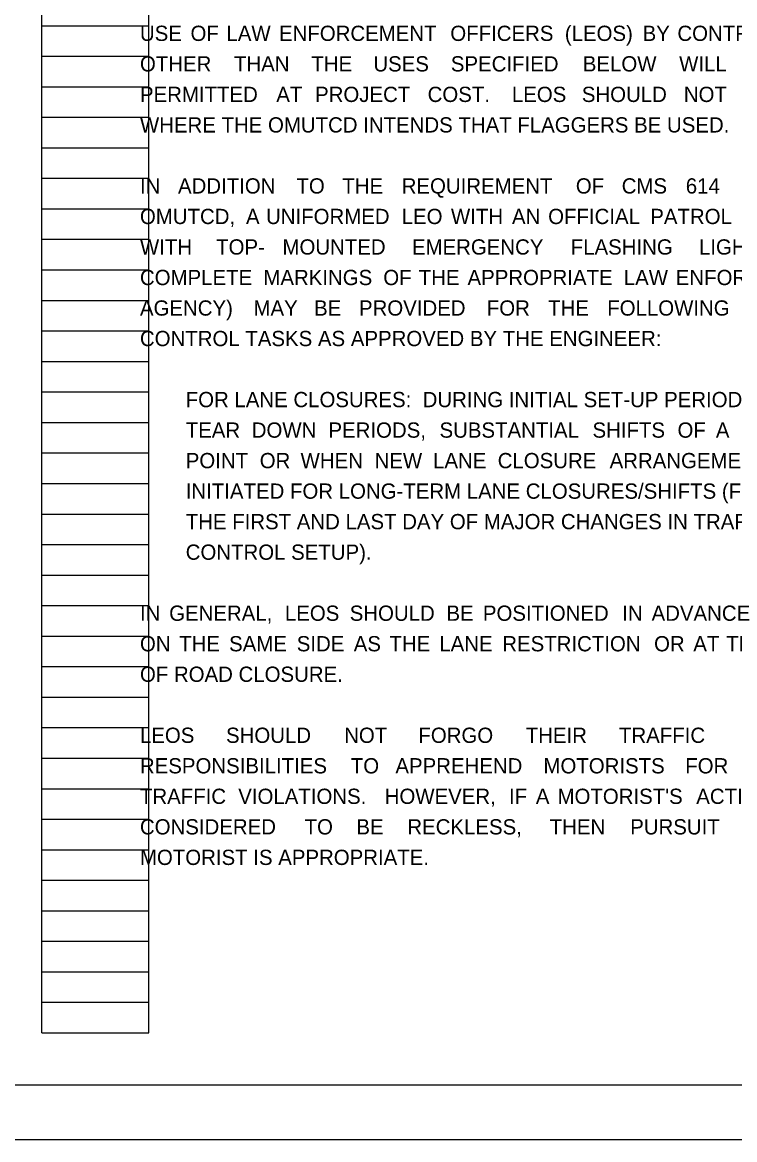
# Model space of a CAD drawing. Extents: x 0 to 34, y 0 to 22.
# Drawn here: x 23.5 to 30.04, y 0 to 10.25 of the extents above; entities that cross this region are included whole.
import ezdxf

# ---------------------------------------------------------------- set-up
doc = ezdxf.new("R2010")
doc.units = 0
for name, color, linetype in [('SH_Border', 7, 'Continuous'), ('SH_Cut_Line', 7, 'Continuous'), ('SH_Data', 7, 'Continuous'), ('SH_Text', 7, 'Continuous')]:
    doc.layers.add(name, color=color, linetype=linetype)

msp = doc.modelspace()

# ---------------------------------------------------------------- linework, layer by layer
at = {"layer": 'SH_Border'}
msp.add_lwpolyline([(1.5, 21.5), (33.5, 21.5), (33.5, 0.5), (1.5, 0.5)], close=True, dxfattribs=at)
at = {"layer": 'SH_Cut_Line'}
msp.add_lwpolyline([(0, 0), (34, 0), (34, 22), (0, 22)], close=True, dxfattribs=at)
at = {"layer": 'SH_Data'}
for p, q in [((23.68, 0.98), (23.68, 21.14)), ((24.66, 0.98), (24.66, 21.14)), ((23.68, 10.22), (24.66, 10.22)), ((23.68, 9.94), (24.66, 9.94)), ((23.68, 9.66), (24.66, 9.66)), ((23.68, 9.38), (24.66, 9.38)), ((23.68, 9.1), (24.66, 9.1)), ((23.68, 8.82), (24.66, 8.82)), ((23.68, 8.54), (24.66, 8.54)), ((23.68, 8.26), (24.66, 8.26)), ((23.68, 7.98), (24.66, 7.98)), ((23.68, 7.7), (24.66, 7.7)), ((23.68, 7.42), (24.66, 7.42)), ((23.68, 7.14), (24.66, 7.14)), ((23.68, 6.86), (24.66, 6.86)), ((23.68, 6.58), (24.66, 6.58)), ((23.68, 6.3), (24.66, 6.3)), ((23.68, 6.02), (24.66, 6.02)), ((23.68, 5.74), (24.66, 5.74)), ((23.68, 5.46), (24.66, 5.46)), ((23.68, 5.18), (24.66, 5.18)), ((23.68, 4.9), (24.66, 4.9)), ((23.68, 4.62), (24.66, 4.62)), ((23.68, 4.34), (24.66, 4.34)), ((23.68, 4.06), (24.66, 4.06)), ((23.68, 3.78), (24.66, 3.78)), ((23.68, 3.5), (24.66, 3.5)), ((23.68, 3.22), (24.66, 3.22)), ((23.68, 2.94), (24.66, 2.94)), ((23.68, 2.66), (24.66, 2.66)), ((23.68, 2.38), (24.66, 2.38)), ((23.68, 2.1), (24.66, 2.1)), ((23.68, 1.82), (24.66, 1.82)), ((23.68, 1.54), (24.66, 1.54)), ((23.68, 1.26), (24.66, 1.26)), ((23.68, 0.98), (24.66, 0.98))]:
    msp.add_line(p, q, dxfattribs=at)

# ---------------------------------------------------------------- texts
at = {"layer": 'SH_Text'}
for s, p in [('USE ', (24.58, 10.08)), ('OF ', (25.044, 10.08)), ('LAW ', (25.374, 10.08)), ('ENFORCEMENT ', (25.856, 10.08)), ('OFFICERS ', (27.428, 10.08)), ('(LEOS) ', (28.479, 10.08)), ('BY ', (29.193, 10.08)), ('CONTRACTORS ', (29.512, 10.08)), ('OTHER ', (24.58, 9.8)), ('THAN ', (25.443, 9.8)), ('THE ', (26.153, 9.8)), ('USES ', (26.722, 9.8)), ('SPECIFIED ', (27.433, 9.8)), ('BELOW ', (28.644, 9.8)), ('WILL ', (29.528, 9.8)), ('PERMITTED ', (24.58, 9.52)), ('AT ', (25.831, 9.52)), ('PROJECT ', (26.187, 9.52)), ('COST.  ', (27.22, 9.52)), ('LEOS ', (27.993, 9.52)), ('SHOULD ', (28.635, 9.52)), ('NOT ', (29.571, 9.52)), ('WHERE THE OMUTCD INTENDS THAT FLAGGERS BE USED.', (24.58, 9.24)), ('IN ', (24.58, 8.68)), ('ADDITION ', (24.929, 8.68)), ('TO ', (26.016, 8.68)), ('THE ', (26.437, 8.68)), ('REQUIREMENT ', (26.982, 8.68)), ('OF ', (28.58, 8.68)), ('CMS ', (29.001, 8.68)), ('614 ', (29.589, 8.68)), ('OMUTCD, ', (24.58, 8.4)), ('A ', (25.553, 8.4)), ('UNIFORMED ', (25.737, 8.4)), ('LEO ', (26.982, 8.4)), ('WITH ', (27.434, 8.4)), ('AN ', (27.994, 8.4)), ('OFFICIAL ', (28.326, 8.4)), ('PATROL ', (29.263, 8.4)), ('WITH ', (24.58, 8.12)), ('TOP-', (25.279, 8.12)), ('MOUNTED ', (25.888, 8.12)), ('EMERGENCY ', (27.076, 8.12)), ('FLASHING ', (28.533, 8.12)), ('LIGHTS ', (29.71, 8.12)), ('COMPLETE ', (24.58, 7.84)), ('MARKINGS ', (25.713, 7.84)), ('OF ', (26.813, 7.84)), ('THE ', (27.138, 7.84)), ('APPROPRIATE ', (27.586, 7.84)), ('LAW ', (29.02, 7.84)), ('ENFORCEMENT ', (29.497, 7.84)), ('AGENCY) ', (24.58, 7.56)), ('MAY ', (25.622, 7.56)), ('BE ', (26.178, 7.56)), ('PROVIDED ', (26.59, 7.56)), ('FOR ', (27.763, 7.56)), ('THE ', (28.326, 7.56)), ('FOLLOWING ', (28.868, 7.56)), ('CONTROL TASKS AS APPROVED BY THE ENGINEER:', (24.58, 7.28)), ('FOR LANE CLOSURES:  DURING INITIAL SET-UP PERIODS, ', (25, 6.72)), ('TEAR ', (25, 6.44)), ('DOWN ', (25.606, 6.44)), ('PERIODS, ', (26.31, 6.44)), ('SUBSTANTIAL ', (27.329, 6.44)), ('SHIFTS ', (28.733, 6.44)), ('OF ', (29.513, 6.44)), ('A ', (29.865, 6.44)), ('POINT ', (25, 6.16)), ('OR ', (25.679, 6.16)), ('WHEN ', (26.054, 6.16)), ('NEW ', (26.733, 6.16)), ('LANE ', (27.27, 6.16)), ('CLOSURE ', (27.863, 6.16)), ('ARRANGEMENTS ', (28.89, 6.16)), ('INITIATED FOR LONG-TERM LANE CLOSURES/SHIFTS (FOR ', (25, 5.88)), ('THE FIRST AND LAST DAY OF MAJOR CHANGES IN TRAFFIC ', (25, 5.6)), ('CONTROL SETUP).', (25, 5.32)), ('IN ', (24.58, 4.76)), ('GENERAL, ', (24.848, 4.76)), ('LEOS ', (25.91, 4.76)), ('SHOULD ', (26.505, 4.76)), ('BE ', (27.393, 4.76)), ('POSITIONED ', (27.727, 4.76)), ('IN ', (29.006, 4.76)), ('ADVANCE ', (29.275, 4.76)), ('ON ', (24.58, 4.48)), ('THE ', (24.94, 4.48)), ('SAME ', (25.398, 4.48)), ('SIDE ', (26.019, 4.48)), ('AS ', (26.542, 4.48)), ('THE ', (26.87, 4.48)), ('LANE ', (27.327, 4.48)), ('RESTRICTION ', (27.905, 4.48)), ('OR ', (29.298, 4.48)), ('AT ', (29.658, 4.48)), ('THE ', (29.96, 4.48)), ('OF ROAD CLOSURE.', (24.58, 4.2)), ('LEOS ', (24.58, 3.64)), ('SHOULD ', (25.37, 3.64)), ('NOT ', (26.454, 3.64)), ('FORGO ', (27.135, 3.64)), ('THEIR ', (28.12, 3.64)), ('TRAFFIC ', (28.976, 3.64)), ('RESPONSIBILITIES ', (24.58, 3.36)), ('TO ', (26.515, 3.36)), ('APPREHEND ', (26.924, 3.36)), ('MOTORISTS ', (28.283, 3.36)), ('FOR ', (29.584, 3.36)), ('TRAFFIC ', (24.58, 3.08)), ('VIOLATIONS.  ', (25.482, 3.08)), ('HOWEVER, ', (26.826, 3.08)), ('IF ', (27.967, 3.08)), ('A ', (28.213, 3.08)), ("MOTORIST'S ", (28.412, 3.08)), ('ACTIONS ', (29.685, 3.08)), ('CONSIDERED ', (24.58, 2.8)), ('TO ', (26.091, 2.8)), ('BE ', (26.566, 2.8)), ('RECKLESS, ', (27.034, 2.8)), ('THEN ', (28.34, 2.8)), ('PURSUIT ', (29.079, 2.8)), ('MOTORIST IS APPROPRIATE.', (24.58, 2.52))]:
    msp.add_text(s, height=0.14, dxfattribs=at).set_placement(p)

doc.saveas('drawing.dxf')
